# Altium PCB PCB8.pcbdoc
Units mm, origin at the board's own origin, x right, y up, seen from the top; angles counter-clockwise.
Board outline 132 x 50 mm, 2 copper layers (Top Layer, Bottom Layer); 16 components, 49 nets, 108 pads, 36 vias.
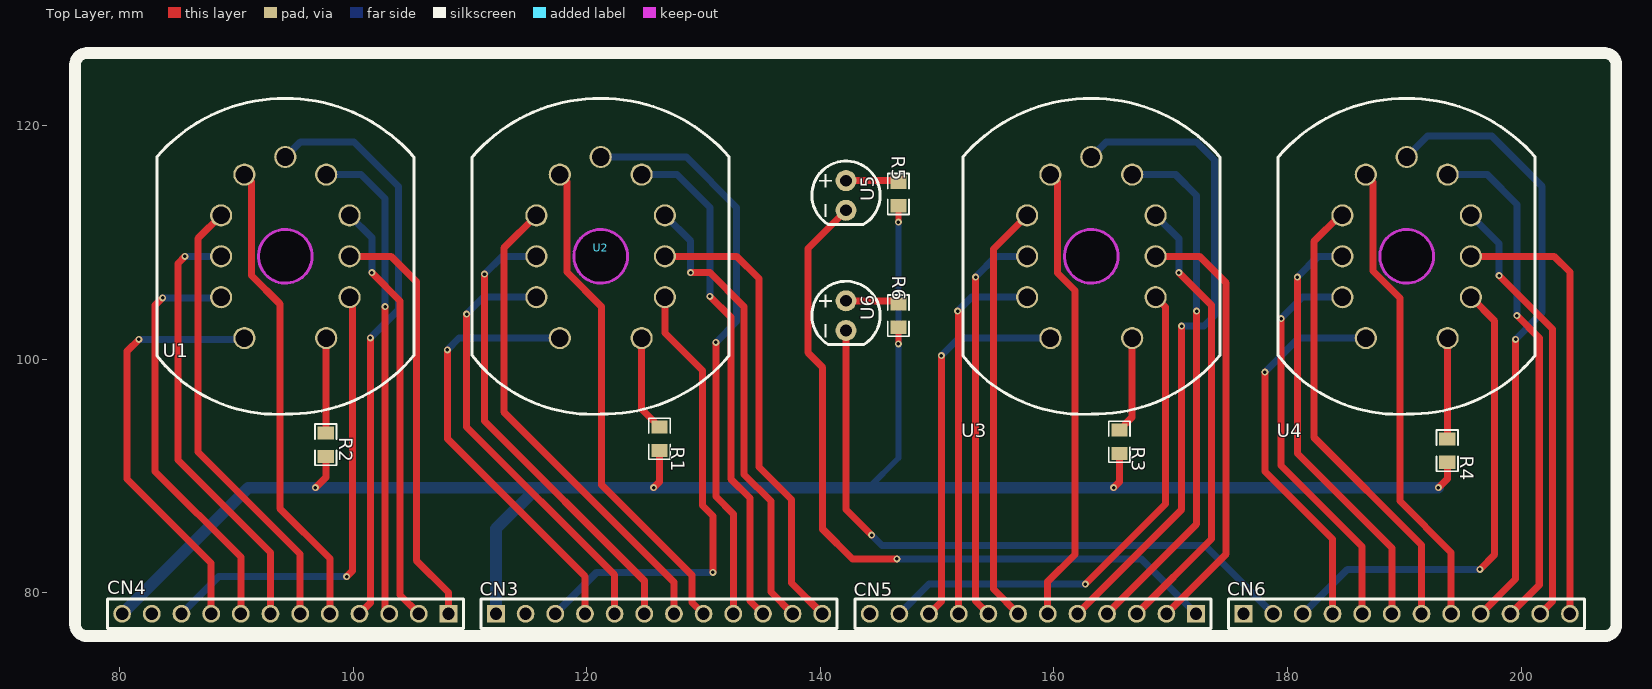
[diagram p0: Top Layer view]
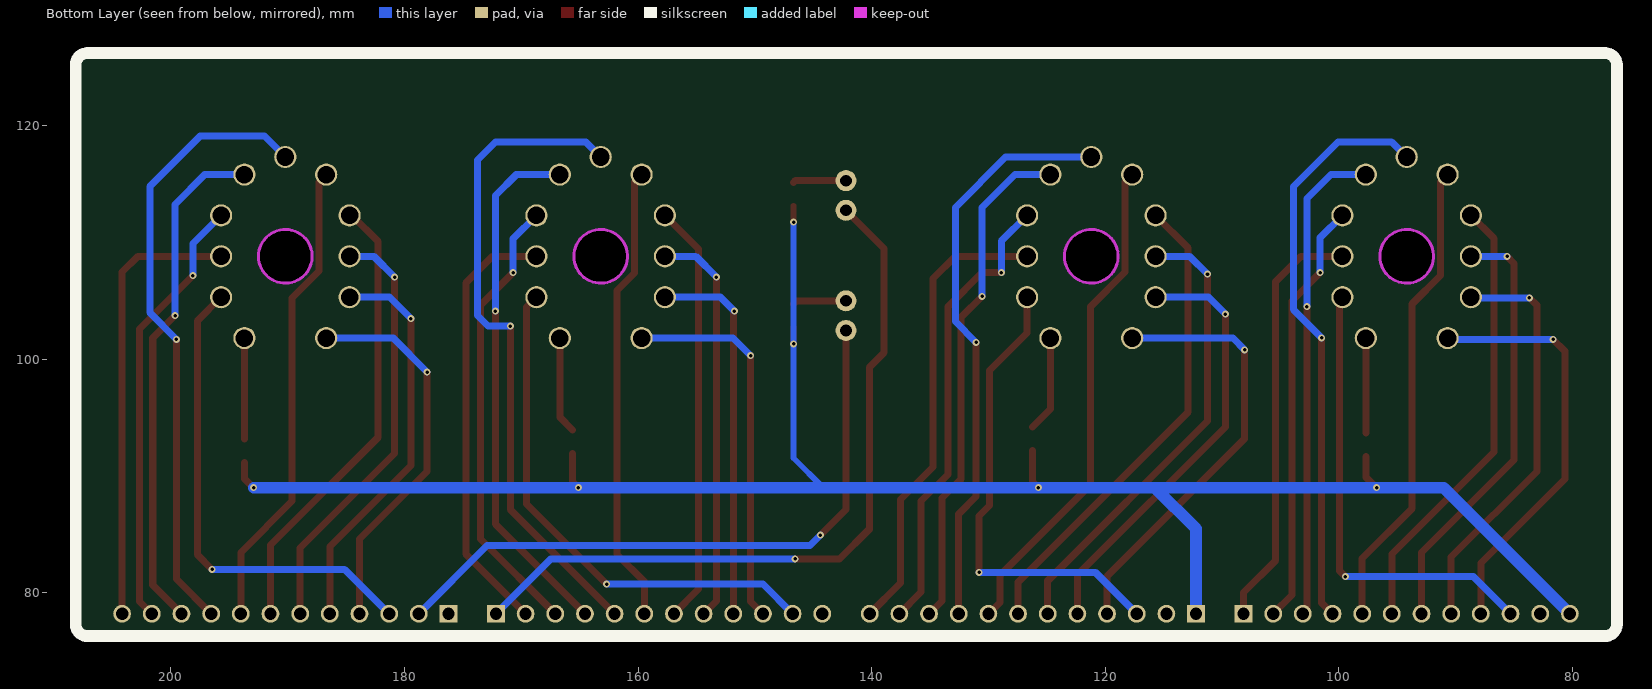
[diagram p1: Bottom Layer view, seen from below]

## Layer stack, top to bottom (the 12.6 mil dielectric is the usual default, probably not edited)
Top Layer: signal copper (thickness not stored)
Dielectric: dielectric 0.32, FR-4, Dk 4.8
Bottom Layer: signal copper (thickness not stored)

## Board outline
77.2,126.2 207.2,126.2 cw(c207.2,125.2) 208.2,125.2 208.2,77.2 cw(c207.2,77.2) 207.2,76.2 77.2,76.2 cw(c77.2,77.2) 76.2,77.2 76.2,125.2 cw(c77.2,125.2)

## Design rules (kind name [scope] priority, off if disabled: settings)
Clearance copperThickness1oz [All] p1: gap=0.178 ignorepadtopadclearanceinfootprint=FALSE except(0.102: Track-Track; 0.152: Track-SMDPad SMDPad-SMDPad Track-THPad SMDPad-THPad THPad-THPad Track-Via SMDPad-Via THPad-Via Via-Via Track-Fill SMDPad-Fill THPad-Fill Via-Fill Fill-Fill Track-Region SMDPad-Region THPad-Region Via-Region Fill-Region Region-Region Track-Poly SMDPad-Poly THPad-Poly Via-Poly Fill-Poly Region-Poly Poly-Poly Track-Text SMDPad-Text THPad-Text Via-Text Fill-Text Region-Text Poly-Text Text-Text Track-Hole SMDPad-Hole THPad-Hole Via-Hole Fill-Hole Region-Hole Poly-Hole Text-Hole; 0.3: Track-Sheet SMDPad-Sheet THPad-Sheet Via-Sheet Fill-Sheet Region-Sheet Poly-Sheet Text-Sheet Sheet-Hole)
Clearance copperThickness2oz [All] p1: gap=0.178 ignorepadtopadclearanceinfootprint=FALSE except(0.152: Track-SMDPad SMDPad-SMDPad Track-THPad SMDPad-THPad THPad-THPad Track-Via SMDPad-Via THPad-Via Via-Via Track-Fill SMDPad-Fill THPad-Fill Via-Fill Fill-Fill Track-Region SMDPad-Region THPad-Region Via-Region Fill-Region Region-Region Track-Poly SMDPad-Poly THPad-Poly Via-Poly Fill-Poly Region-Poly Poly-Poly Track-Text SMDPad-Text THPad-Text Via-Text Fill-Text Region-Text Poly-Text Text-Text Track-Hole SMDPad-Hole THPad-Hole Via-Hole Fill-Hole Region-Hole Poly-Hole Text-Hole; 0.203: Track-Track; 0.3: Track-Sheet SMDPad-Sheet THPad-Sheet Via-Sheet Fill-Sheet Region-Sheet Poly-Sheet Text-Sheet Sheet-Hole)
DiffPairsRouting differentialPair [All] p1: maxuncoupledlength=10 maxlimit=5.9843 mostfreqgap=5.9843 toplayer_minwidth=5 toplayer_prefwidth=10 toplayer_maxwidth=100 bottomlayer_minwidth=5 bottomlayer_prefwidth=10 bottomlayer_maxwidth=100
PasteMaskExpansion pasteMaskExpansion [All] p1:
PlaneConnect innerPlane [All] p1: planeconnectstyle=Relief reliefexpansion=0.508 reliefentries=4 reliefconductorwidth=0.254 reliefairgap=0.254
PolygonConnect copperRegion [All] p1: connectstyle=Direct reliefentries=4 reliefconductorwidth=10 polygonreliefangle="90 Angle" airgapwidth=10
RoutingVias viaSize [All] p1: viastyle="Through Hole" holewidth=12.0078 minholewidth=11.811 maxholewidth=248.0314 width=24.0158 minwidth=19.685 maxwidth=393.7008
SolderMaskExpansion solderMaskExpansion [All] p1: useseparateexpansions=TRUE expansion=2.0079 expansionbottom=2.0079
Width copperThickness1oz [All] p1: maxlimit=100 minlimit=5 preferedwidth=10
Width copperThickness2oz [All] p1: maxlimit=100 minlimit=8 preferedwidth=10

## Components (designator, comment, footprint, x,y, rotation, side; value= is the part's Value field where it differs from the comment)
CN3 "HB-PH3-254112PB2GOP" HDR-TH_12P-P2.54-V-M 126.2,78.2 r0 top
CN4 "HB-PH3-254112PB2GOP" HDR-TH_12P-P2.54-V-M 94.2,78.2 r180 top
CN5 "HB-PH3-254112PB2GOP" HDR-TH_12P-P2.54-V-M 158.2,78.2 r180 top
CN6 "HB-PH3-254112PB2GOP" HDR-TH_12P-P2.54-V-M 190.2,78.2 r0 top
R1 "0805W8F3302T5E" R0805 126.238,93.18 r270 top
R2 "0805W8F3302T5E" R0805 97.663,92.672 r270 top
R3 "0805W8F3302T5E" R0805 165.608,92.926 r270 top
R4 "0805W8F3302T5E" R0805 193.675,92.164 r270 top
R5 "0805W8F4702T5E" R0805 146.685,114.135 r270 top
R6 "0805W8F4702T5E" R0805 146.685,103.721 r270 top
U1 "QS27.1" QS27 94.2,108.801 r0 top
U2 "QS27.1" QS27 121.2,108.801 r0 top
U3 "QS27.1" QS27 163.2,108.801 r0 top
U4 "QS27.1" QS27 190.2,108.801 r0 top
U5 "LTL-307E" LED-TH_BD5.9-P2.54-RD_RED 142.2,114.008 r90 top
U6 "LTL-307E" LED-TH_BD5.9-P2.54-RD_RED 142.2,103.721 r90 top

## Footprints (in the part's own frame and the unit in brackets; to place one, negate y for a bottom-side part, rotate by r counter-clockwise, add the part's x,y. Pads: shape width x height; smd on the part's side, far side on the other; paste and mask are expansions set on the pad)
HDR-TH_12P-P2.54-V-M [mil]
  rect 60x60 hole 41.34: 1(-550,0)
  round 60 hole 41.34: 2(-450,0) 3(-350,0) 4(-250,0) 5(-150,0) 6(-50,0) 7(50,0) 8(150,0) 9(250,0) 10(350,0) 11(450,0) 12(550,0)
  silkscreen extent -600,-50 600,50
LED-TH_BD5.9-P2.54-RD_RED [mm]
  round 1.8 hole 1: 1(-1.27,0) 2(1.27,0)
  silkscreen extent -2.49,-2.92 2.94,2.92
QS27 [mm]
  round 1.9 hole 1.5: 1(3.5,-7) 2(5.5,-3.5) 3(5.5,0) 4(5.5,3.5) 5(3.5,7) 6(0,8.5) 7(-3.5,7) 8(-5.5,3.5) 9(-5.5,0) 10(-5.5,-3.5) 11(-3.5,-7)
  Multi-Layer board cut-out: 2.3,0 2.072,0.998 1.434,1.798 0.512,2.242 -0.512,2.242 -1.434,1.798 -2.072,0.998 -2.3,0 -2.3,0 -1.992,-1.15 -1.15,-1.992 0,-2.3 1.15,-1.992 1.992,-1.15 2.3,0
  Multi-Layer keep-out circle w0.254: c0,0 r2.3
  silkscreen extent -11,-13.52 11,13.5
R0805 [mm]
  rect 1.133x1.377 smd: 1(-1,0) 2(1,0)
  silkscreen extent -1.76,-0.92 1.76,0.92

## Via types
v1: diameter 0.6, hole 0.3, Top Layer to Bottom Layer, 36 vias

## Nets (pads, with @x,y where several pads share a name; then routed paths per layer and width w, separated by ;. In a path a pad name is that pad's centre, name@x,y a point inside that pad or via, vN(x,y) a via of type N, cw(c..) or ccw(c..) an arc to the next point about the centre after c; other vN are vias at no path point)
$1N2845: R2.1 U1.1 | length 8.1
  Top Layer w0.6: R2.1 97.7,93.709 U1.1
$1N2867: R3.1 U3.1 | length 8.3
  Top Layer w0.6: R3.1 166.7,95.018 U3.1
$1N3020: R5.1 U5.2 | length 4.5
  Top Layer w0.6: U5.2 146.542,115.278 R5.1
$1N3024: R6.1 U6.2 | length 4.6
  Top Layer w0.6: U6.2 146.415,104.991 R6.1
$1N3056: R1.1 U2.1 | length 8.3
  Top Layer w0.6: U2.1 124.7,95.718 R1.1
$1N3057: R4.1 U4.1 | length 8.6
  Top Layer w0.6: R4.1 193.675,101.776 U4.1
G1_0: CN4.10 U1.2 | length 39.7
  Top Layer w0.6: v1(99.441,81.369) 99.949,81.877 99.949,105.052 U1.2
  Bottom Layer w0.6: CN4.10 88.479,81.369 v1(99.441,81.369)
G1_1: CN4.9 U1.11 | length 36
  Top Layer w0.6: v1(81.661,101.689) 80.645,100.673 80.645,89.751 87.85,82.546 CN4.9
  Bottom Layer w0.6: v1(81.661,101.689) 90.588,101.689 U1.11
G1_2: CN4.8 U1.10 | length 35.4
  Top Layer w0.6: v1(83.693,105.245) 83.058,104.61 83.058,90.386 90.39,83.054 CN4.8
  Bottom Layer w0.6: v1(83.693,105.245) 88.644,105.245 U1.10
G1_3: CN4.7 U1.9 | length 37.2
  Top Layer w0.6: v1(85.598,108.801) 84.998,108.201 84.998,91.367 92.93,83.435 CN4.7
  Bottom Layer w0.6: v1(85.598,108.801) U1.9
G1_4: CN4.6 U1.8 | length 38.5
  Top Layer w0.6: U1.8 86.741,110.342 86.741,92.037 95.47,83.308 CN4.6
G1_5: CN4.5 U1.7 | length 40.6
  Top Layer w0.6: U1.7 91.3,115.201 91.3,107.163 93.726,104.737 93.726,87.211 98.01,82.927 CN4.5
G1_6: CN4.4 U1.6 | length 49.7
  Top Layer w0.6: CN4.4 101.473,79.123 v1(101.473,101.816)
  Bottom Layer w0.6: U1.6 95.479,118.58 100.076,118.58 103.886,114.77 103.886,104.229 v1(101.473,101.816)
G1_7: CN4.3 U1.5 | length 41.6
  Top Layer w0.6: v1(102.743,104.483) 102.743,78.547 CN4.3@103.089,78.201
  Bottom Layer w0.6: U1.5 100.696,115.801 102.743,113.754 v1(102.743,104.483)
G1_8: 
G1_9: CN4.1 U1.3 | length 36.2
  Top Layer w0.6: U1.3 103.251,108.801 105.41,106.642 105.41,82.766 108.17,80.006 CN4.1
G2_0: CN3.3 U2.2 | length 40.2
  Top Layer w0.6: U2.2 126.7,102.243 129.921,99.022 129.921,87.465 130.81,86.576 v1(130.81,81.75)
  Bottom Layer w0.6: CN3.3 120.86,81.75 v1(130.81,81.75)
G2_1: CN3.4 U2.11 | length 37.5
  Top Layer w0.6: v1(108.077,100.8) 108.077,93.18 119.85,81.407 CN3.4
  Bottom Layer w0.6: v1(108.077,100.8) 109.078,101.801 U2.11
G2_2: CN3.5 U2.10 | length 37.5
  Top Layer w0.6: v1(109.728,103.848) 109.728,94.196 122.39,81.534 CN3.5
  Bottom Layer w0.6: v1(109.728,103.848) 111.181,105.301 U2.10
G2_3: CN3.6 U2.9 | length 39.8
  Top Layer w0.6: v1(111.252,107.277) 111.252,94.704 124.93,81.026 CN3.6
  Bottom Layer w0.6: v1(111.252,107.277) 112.776,108.801 U2.9
G2_4: CN3.7 U2.8 | length 41.3
  Top Layer w0.6: U2.8 112.903,109.504 112.903,95.466 127.47,80.899 CN3.7
G2_5: CN3.8 U2.7 | length 42.7
  Top Layer w0.6: U2.7 118.3,115.201 118.3,107.468 121.285,104.483 121.285,89.243 129.032,81.496 129.032,79.178 CN3.8
G2_6: CN3.9 U2.6 | length 49.6
  Top Layer w0.6: v1(131.064,101.435) 131.064,88.227 132.55,86.741 CN3.9
  Bottom Layer w0.6: U2.6 128.533,117.301 132.842,112.992 132.842,103.213 v1(131.064,101.435)
G2_7: CN3.10 U2.5 | length 43.7
  Top Layer w0.6: v1(130.556,105.372) 132.334,103.594 132.334,89.751 133.985,88.1 133.985,79.305 CN3.10
  Bottom Layer w0.6: U2.5 127.747,115.801 130.556,112.992 v1(130.556,105.372)
G2_8: CN3.11 U2.4 | length 39.6
  Top Layer w0.6: v1(128.905,107.404) 130.556,107.404 133.477,104.483 133.477,90.132 135.763,87.846 135.763,80.067 CN3.11
  Bottom Layer w0.6: U2.4 128.905,110.096 v1(128.905,107.404)
G2_9: CN3.12 U2.3 | length 39.8
  Top Layer w0.6: U2.3 132.842,108.801 134.747,106.896 134.747,90.767 137.541,87.973 137.541,80.829 CN3.12
G3_0: CN5.11 U3.2 | length 44.7
  Top Layer w0.6: v1(162.687,80.734) 169.545,87.592 169.545,104.456 U3.2
  Bottom Layer w0.6: CN5.11 149.304,80.734 v1(162.687,80.734)
G3_1: CN5.10 U3.11 | length 32.5
  Top Layer w0.6: CN5.10 150.368,79.258 v1(150.368,100.292)
  Bottom Layer w0.6: v1(150.368,100.292) 151.877,101.801 U3.11
G3_2: CN5.9 U3.10 | length 32.4
  Top Layer w0.6: v1(151.765,104.102) 151.85,104.017 CN5.9
  Bottom Layer w0.6: v1(151.765,104.102) 152.964,105.301 U3.10
G3_3: CN5.8 U3.9 | length 34.4
  Top Layer w0.6: v1(153.289,107.023) 153.289,79.301 CN5.8
  Bottom Layer w0.6: v1(153.289,107.023) 155.067,108.801 U3.9
G3_4: CN5.7 U3.8 | length 36.2
  Top Layer w0.6: CN5.7 154.813,80.317 154.813,109.414 U3.8
G3_5: CN5.6 U3.7 | length 39.4
  Top Layer w0.6: CN5.6 159.47,80.946 161.798,83.274 161.798,105.88 160.3,107.378 160.3,115.201 U3.7
G3_6: CN5.5 U3.6 | length 56.5
  Top Layer w0.6: CN5.5 170.942,87.132 v1(170.942,102.832)
  Bottom Layer w0.6: U3.6 164.479,118.58 172.212,118.58 173.736,117.056 173.736,103.721 172.847,102.832 v1(170.942,102.832)
G3_7: CN5.4 U3.5 | length 45.2
  Top Layer w0.6: CN5.4 172.212,85.862 v1(172.212,104.102)
  Bottom Layer w0.6: U3.5 166.715,115.786 170.434,115.786 172.212,114.008 v1(172.212,104.102)
G3_8: CN5.3 U3.4 | length 38.7
  Top Layer w0.6: CN5.3 173.482,84.592 173.482,104.61 v1(170.688,107.404)
  Bottom Layer w0.6: U3.4 170.688,110.313 v1(170.688,107.404)
G3_9: CN5.2 U3.3 | length 37.4
  Top Layer w0.6: U3.3 172.466,108.801 174.752,106.515 174.752,83.322 CN5.2
G4_0: CN6.3 U4.2 | length 41.4
  Top Layer w0.6: U4.2 197.739,103.262 197.739,83.274 v1(196.469,82.004)
  Bottom Layer w0.6: CN6.3 185.114,82.004 v1(196.469,82.004)
G4_1: CN6.4 U4.11 | length 32.9
  Top Layer w0.6: v1(178.054,98.895) 178.054,90.386 183.85,84.59 CN6.4
  Bottom Layer w0.6: v1(178.054,98.895) 180.96,101.801 U4.11
G4_2: CN6.5 U4.10 | length 34.1
  Top Layer w0.6: v1(179.451,103.467) 179.451,90.894 186.39,83.955 CN6.5
  Bottom Layer w0.6: v1(179.451,103.467) 181.285,105.301 U4.10
G4_3: CN6.6 U4.9 | length 36.8
  Top Layer w0.6: v1(180.848,107.023) 180.848,91.91 188.93,83.828 CN6.6
  Bottom Layer w0.6: v1(180.848,107.023) 182.626,108.801 U4.9
G4_4: CN6.7 U4.8 | length 39.1
  Top Layer w0.6: U4.8 184.475,112.301 182.245,110.071 182.245,93.307 191.47,84.082 CN6.7
G4_5: CN6.8 U4.7 | length 40.6
  Top Layer w0.6: U4.7 187.325,115.176 187.325,107.531 189.611,105.245 189.611,87.846 194.01,83.447 CN6.8
G4_6: CN6.9 U4.6 | length 52.9
  Top Layer w0.6: CN6.9 199.517,81.167 v1(199.517,101.689)
  Bottom Layer w0.6: U4.6 191.987,119.088 197.485,119.088 201.803,114.77 201.803,103.975 v1(199.517,101.689)
G4_7: CN6.10 U4.5 | length 43.9
  Top Layer w0.6: CN6.10 201.549,80.659 201.549,101.816 v1(199.644,103.721)
  Bottom Layer w0.6: U4.5 193.715,115.786 197.104,115.786 199.644,113.246 v1(199.644,103.721)
G4_8: CN6.11 U4.4 | length 37.4
  Top Layer w0.6: v1(198.12,107.15) 202.692,102.578 202.692,79.262 CN6.11
  Bottom Layer w0.6: U4.4 198.12,109.881 v1(198.12,107.15)
G4_9: CN6.12 U4.3 | length 38.3
  Top Layer w0.6: U4.3 202.819,108.801 204.17,107.45 CN6.12
HGD_1: CN5.1 U5.1 | length 64.1
  Top Layer w0.6: U5.1 138.938,109.476 138.938,100.546 140.208,99.276 140.208,85.433 142.748,82.893 v1(146.558,82.893)
  Bottom Layer w0.6: v1(146.558,82.893) 167.477,82.893 CN5.1
HGD_2: CN6.2 U6.1 | length 55.6
  Top Layer w0.6: U6.1 142.2,87.124 v1(144.399,84.925)
  Bottom Layer w0.6: v1(144.399,84.925) 145.288,84.036 172.934,84.036 CN6.2
HV: CN3.1 CN4.12 R1.2 R2.2 R3.2 R4.2 R5.2 R6.2 | length 168.1
  Top Layer w0.5: v1(146.685,101.308) R6.2 ; v1(146.685,111.722) R5.2
  Top Layer w0.6: v1(96.774,88.989) 97.663,89.878 R2.2 ; v1(125.73,88.989) 126.238,89.497 R1.2 ; v1@165.1,88.989 165.608,89.497 R3.2 ; v1(192.913,88.989) 193.675,89.751 R4.2
  Bottom Layer w0.5: 144.145,88.989 146.685,91.529 v1(146.685,101.308) v1(146.685,111.722)
  Bottom Layer w1: CN4.12 91.019,88.989 v1(96.774,88.989) 115.753,88.989 ; CN3.1 112.23,85.466 115.753,88.989 ; v1(192.913,88.989) v1(165.102,88.989) 144.145,88.989 v1(125.73,88.989) 115.753,88.989
pads on no net: CN3.2 CN4.2 CN4.11 CN5.12 CN6.1 U1.4
copper on no net: | length 36.6
  Top Layer w0.6: v1(101.6,107.404) 104.013,104.991 104.013,79.817 105.63,78.2
  Bottom Layer w0.6: 99.7,112.301 101.6,110.401 v1(101.6,107.404)

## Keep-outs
Board Outline Layer:
  the board outline again, w0.254

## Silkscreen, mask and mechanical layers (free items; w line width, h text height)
Top Silkscreen Layer:
  lines w1: 76.2,77.289 ccw(c77.2,77.289) 77.2,76.289 207.153,76.289 ccw(c207.153,77.289) 208.153,77.289 208.153,125.2 ccw(c207.153,125.2) 207.153,126.2 77.2,126.2 ccw(c77.2,125.2) 76.2,125.2 76.2,77.289
Bottom Silkscreen Layer:
  lines w1: 76.2,77.289 ccw(c77.2,77.289) 77.2,76.289 207.153,76.289 ccw(c207.153,77.289) 208.153,77.289 208.153,125.2 ccw(c207.153,125.2) 207.153,126.2 77.2,126.2 ccw(c77.2,125.2) 76.2,125.2 76.2,77.289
